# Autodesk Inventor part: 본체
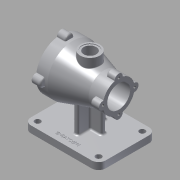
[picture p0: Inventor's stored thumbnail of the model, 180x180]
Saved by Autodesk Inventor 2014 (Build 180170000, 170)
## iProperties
Created: 2020-12
Part Number: 본체
Material: 알루미늄 6061
Document SubType Name: Modeling
Designer: kh
Density: 2.71 g/cm^3
Appearance: 알루미늄 - 평지
Mass: 1037.41 g
Surface Area: 870.977 cm^2
Volume: 382.81 cm^3
Author: kh
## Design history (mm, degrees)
sketch "스케치2"
  geometry: L1 (65, 50)-(-65, 50); L2 (-65, 50)-(-65, -50); L3 (-65, -50)-(65, -50); L4 (65, -50)-(65, 50); L5 (65, 50)-(-65, -50); L6 (-65, 50)-(65, -50); 1 further point
  constraints: 12 end point, 2 midpoint, 2 parallel, 1 horizontal, 1 perpendicular
  dimensions: "d0" = 130 distance between parallel lines of L4 L2; "d1" = 100 distance between parallel lines of L3 L1
extrude "돌출1" new body sketch "스케치2" distance "d2" = 12; taper "d3" = 0 deg
fillet "모깎기1" dims "d4" = 12
sketch "스케치3"
  geometry: L1 (-65, 38)-(-65, -38) reference; L2 (-53, -50)-(53, -50) reference; L3 (65, -38)-(65, 38) reference; L4 (53, 50)-(-53, 50) reference; C1 r 5 at (-53, 38); C2 r 5 at (-53, -38); C3 r 5 at (53, 38); C4 r 5 at (53, -38); A1 r 12 centre (-53, 38) between (-53, 50) and (-65, 38) reference; A2 r 12 centre (-53, -38) between (-65, -38) and (-53, -50) reference; A3 r 12 centre (53, -38) between (53, -50) and (65, -38) reference; A4 r 12 centre (53, 38) between (65, 38) and (53, 50) reference; 1 further point
  constraints: 4 centre point, 4 coincident
  dimensions: "d5" = 10 diameter of C1; "d6" = 10 diameter of C2; "d7" = 10 diameter of C3; "d8" = 10 diameter of C4
extrude "돌출2" cut sketch "스케치3" distance "d9" = 12; taper "d10" = 0 deg
sketch "스케치4"
  geometry: L1 (0, 0)-(0, 12); L2 (-53, 12)-(53, 12) reference; L3 (-53, 0)-(53, 0) reference; L4 (24, 12)-(24, 62); L5 (24, 62)-(-24, 62); L6 (-24, 62)-(-24, 12); L7 (24, 12)-(-24, 12)
  constraints: 10 end point, 3 midpoint, 3 perpendicular, 2 point on line, 1 collinear, 1 vertical
  dimensions: "d19" = 48 distance between parallel lines of L6 L4; "d20" = 50 distance between parallel lines of L2 L5
extrude "돌출3" join sketch "스케치4" stored distance "d21" = 8; taper "d22" = 0 deg
sketch "스케치5"
  geometry: L1 (38, 12)-(-38, 12) reference; L2 (-25, 12)-(-25, 62); L3 (-25, 62)-(25, 62); L4 (25, 62)-(25, 12); L5 (-25, 12)-(25, 12); 3 further points
  constraints: 8 end point, 4 perpendicular, 2 midpoint, 2 point on line, 1 coincident
  dimensions: "d23" = 50 distance between parallel lines of L4 L2; "d24" = 50 distance between parallel lines of L1 L3
extrude "돌출4" join sketch "스케치5" stored distance "d25" = 8; taper "d26" = 0 deg
sketch "스케치6"
  geometry: L1 (-53, 12)-(53, 12) reference; L2 (-53, 0)-(53, 0) reference; L3 (50, 82)-(-50, 82); L4 (-50, 82)-(-50, 109.5); L5 (-50, 109.5)-(-25, 109.5); L6 (-25, 109.5)-(30, 126); L7 (30, 126)-(50, 126); L8 (50, 126)-(50, 82); 3 further points
  constraints: 12 end point, 4 parallel, 2 midpoint, 1 perpendicular, 1 vertical alignment
  dimensions: "d27" = 88 diameter of L7 L3; "d28" = 55 diameter of L5 L3; "d29" = 20 distance of L6.end L7.end; "d30" = 25 distance of L4.end L5.end; "d32" = 82 distance of point (0, 0) point (0, 82); "d34" = 50 distance from line of point (0, 82) L8
revolve "회전1" sketch "스케치6" stored, may be unused: angle "d33" = 90 deg
node "작업 평면2"
sketch "스케치7"
  geometry: C1 r 17 at (0, 0); 1 further point
  constraints: 1 centre point, 1 coincident
  dimensions: "d37" = 34 diameter of C1
extrude "돌출5" join sketch "스케치7" stored distance "d38" = 8; taper "d39" = 0 deg
sketch "스케치8"
  geometry: C1 r 14 at (0, 0); 1 further point
  constraints: 1 centre point, 1 coincident
  dimensions: "d40" = 28 diameter of C1
extrude "돌출6" cut sketch "스케치8" distance "d41" = 1; taper "d42" = 0 deg
sketch "스케치9"
  geometry: C1 r 11 at (0, 0); 1 further point
  constraints: 1 centre point, 1 coincident
  dimensions: "d44" = 22 diameter of C1
extrude "돌출7" cut sketch "스케치9" distance "d45" = 35; taper "d46" = 0 deg
sketch "스케치12"
  geometry: C1 r 7 at (0, 27.5); C2 r 7 at (-27.5, 0); C3 r 7 at (0, -27.5); C4 r 7 at (27.5, 0); A1 r 27.5 centre (0, 0) between (0, 27.5) and (-27.5, 0) reference; 1 further point
  constraints: 4 centre point, 4 point on circle, 2 horizontal alignment, 2 vertical alignment
  dimensions: "d53" = 14 diameter of C1; "d54" = 14 diameter of C2; "d55" = 14 diameter of C3; "d56" = 14 diameter of C4
extrude "돌출9" join sketch "스케치12" distance "d57" = 15; taper "d58" = 0 deg
sketch "스케치14"
  geometry: C1 r 7.5 at (44, 0); C2 r 7.5 at (0, 44); C3 r 7.5 at (-44, 0); C4 r 7.5 at (0, -44); A1 r 44 centre (0, 0) between (44, 0) and (0, 44) reference; 1 further point
  constraints: 4 centre point, 4 point on circle, 2 horizontal alignment
  dimensions: "d59" = 15 diameter of C1; "d60" = 15 diameter of C2; "d61" = 15 diameter of C3; "d62" = 15 diameter of C4
extrude "돌출10" join sketch "스케치14" distance "d63" = 15; taper "d64" = 0 deg
sketch "스케치15"
  geometry: L1 (-53, 0)-(53, 0) reference; L2 (50, 82)-(-50, 82); L3 (-50, 82)-(-50, 102); L4 (-50, 102)-(-20, 102); L5 (-20, 102)-(-20, 108); L6 (-20, 108)-(27, 108); L7 (27, 108)-(27, 114); L8 (27, 114)-(50, 114); L9 (50, 114)-(50, 82); 3 further points
  constraints: 16 end point, 7 parallel, 2 midpoint, 1 perpendicular, 1 vertical alignment
  dimensions: "d65" = 82 distance of point (0, 0) point (0, 82); "d66" = 64 diameter of L8 L2; "d67" = 23 distance between parallel lines of L7 L9; "d68" = 52 diameter of L6 L2; "d69" = 47 distance between parallel lines of L7 L5; "d70" = 30 distance between parallel lines of L5 L3; "d71" = 40 diameter of L4 L2
revolve "회전2" sketch "스케치15" stored, may be unused: angle "d72" = 90 deg
hole "구멍1" diameter "d75" = 4.134; stored, may be unused: countersink angle "d79" = 90 deg, drill point angle "d81" = 118 deg; dims "d73" = 10, "d74" = 10, "d76" = 9, "d77" = 4, "d78" = 2, "d80" = 11
hole "구멍2" diameter "d84" = 4.134; stored, may be unused: countersink angle "d88" = 90 deg, drill point angle "d90" = 118 deg; dims "d82" = 10, "d83" = 10, "d85" = 9, "d86" = 4, "d87" = 2, "d89" = 11
hole "구멍3" diameter "d93" = 4.134; stored, may be unused: countersink angle "d97" = 90 deg, drill point angle "d99" = 118 deg; dims "d91" = 10, "d92" = 10, "d94" = 9, "d95" = 4, "d96" = 2, "d98" = 11
hole "구멍4" diameter "d102" = 4.134; stored, may be unused: countersink angle "d106" = 90 deg, drill point angle "d108" = 118 deg; dims "d100" = 10, "d101" = 10, "d103" = 9, "d104" = 4, "d105" = 2, "d107" = 11
sketch "스케치16"
  geometry: C1 r 32 at (-44, 0) reference; A1 r 44 centre (-44, 0) between (-36.527, -43.361) and (-0.639, -7.473) reference; A2 r 7.5 centre (0, 0) between (-0.639, -7.473) and (-0.639, 7.473) reference; A3 r 44 centre (-44, 0) between (-0.639, 7.473) and (-36.527, 43.361) reference; A4 r 7.5 centre (-44, 44) between (-36.527, 43.361) and (-51.473, 43.361) reference; A5 r 44 centre (-44, 0) between (-51.473, 43.361) and (-87.361, 7.473) reference; A6 r 7.5 centre (-88, 0) between (-87.361, 7.473) and (-87.361, -7.473) reference; A7 r 44 centre (-44, 0) between (-87.361, -7.473) and (-51.473, -43.361) reference; A8 r 7.5 centre (-44, -44) between (-51.473, -43.361) and (-36.527, -43.361) reference; 5 further points
  constraints: 4 coincident
hole "구멍5" sketch "스케치16" at (-44, 44), (-88, 0), (-44, -44), (0, 0) diameter "d109" = 4.134; stored, may be unused: countersink angle "d113" = 90 deg, drill point angle "d115" = 118 deg; dims "d110" = 9, "d111" = 4, "d112" = 2, "d114" = 11
sketch "스케치17"
  geometry: 2 further points
  constraints: 1 other
feature "엠보싱1" sketch "스케치17" dims "d0" = 130, "d1" = 100, "d116" = 0.5, "d117" = 0
fillet "모깎기5" dims "d121" = 1
fillet "모깎기6" dims "d122" = 3
fillet "모깎기7" dims "d123" = 3
fillet "모깎기8" dims "d124" = 3
fillet "모깎기9" dims "d125" = 3
fillet "모깎기10" dims "d126" = 1
node "솔리드1"
node "투영된 루프1"
node "투영된 루프3"
node "투영된 루프4"
node "투영된 루프5"
other parameters: "d36" = -127
